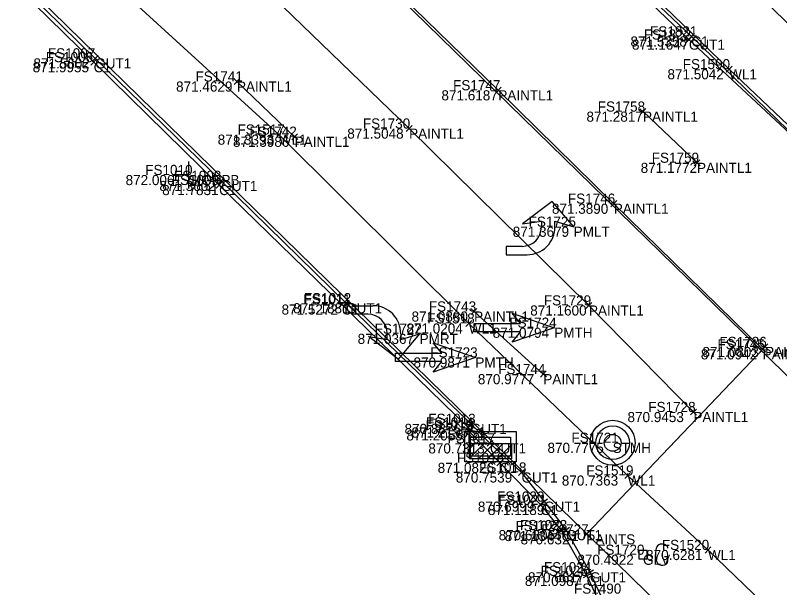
# Model space of a CAD drawing. Extents: x 1469677 to 1493262, y 375219 to 389293.
# Drawn here: x 1479502.2 to 1479592.9, y 379943 to 380010.9 of the extents above; entities that cross this region are included whole.
import ezdxf

# ---------------------------------------------------------------- set-up
doc = ezdxf.new("R2010")
doc.units = 0
for name, color, linetype in [('Building', 7, 'Continuous'), ('DR_X_Drive_Pipe', 7, 'Continuous'), ('DV_X_Text', 7, 'Continuous'), ('GK_Visualization', 7, 'Continuous'), ('PNTELEV', 7, 'Continuous'), ('RD_P_Text', 7, 'Continuous'), ('RW_P_Esmt_SW', 7, 'Continuous'), ('RW_P_Esmt_TMP', 7, 'Continuous'), ('RW_X_CL_20', 7, 'Continuous'), ('rw_x_right_of_way', 7, 'Continuous'), ('RW_X_Text', 7, 'Continuous'), ('SV_X_Mon_Cells_Found', 7, 'Continuous'), ('SV_X_Random_Point', 7, 'Continuous'), ('SV_X_Text', 7, 'Continuous'), ('SV_X_Text_Elevation', 7, 'Continuous')]:
    doc.layers.add(name, color=color, linetype=linetype)

msp = doc.modelspace()

# ---------------------------------------------------------------- linework, layer by layer
at = {"layer": 'Building'}
for points in [[(1479590.899, 379971.251), (1479573.223, 379988.536), (1479559.51, 380001.998), (1479539.567, 380021.405), (1479519.756, 380040.531), (1479501.596, 380058.123), (1479484.932, 380074.195)], [(1479582.673, 379963.807), (1479570.271, 379976.458), (1479548.912, 379997.458), (1479531.64, 380014.197), (1479515.852, 380030.017), (1479497.57, 380047.609), (1479484.703, 380060.356), (1479474.973, 380069.833)], [(1479528.47, 380003.039), (1479535.323, 379996.483)], [(1479576.693, 379999.465), (1479583.102, 379993.389)], [(1479556.633, 379975.739), (1479564.853, 379968.305)]]:
    msp.add_lwpolyline(points, dxfattribs=at)
at = {"layer": 'DR_X_Drive_Pipe'}
for points in [[(1479604.754, 379987.567), (1479586.915, 380004.501), (1479544.961, 380044.963), (1479522.598, 380067.181), (1479502.338, 380087.071)], [(1479473.217, 380054.881), (1479498.741, 380029.974), (1479514.505, 380014.087), (1479533.448, 379996.736), (1479556.003, 379974.32), (1479574.861, 379956.271), (1479584.403, 379947.432), (1479599.597, 379932.82), (1479630.106, 379903.783), (1479644.769, 379889.723), (1479654.209, 379882.356), (1479664.266, 379872.629), (1479692.509, 379845.847), (1479712.672, 379826.686), (1479730.739, 379809.851), (1479753.15, 379788.309), (1479771.842, 379770.542), (1479781.678, 379761.101)]]:
    msp.add_lwpolyline(points, dxfattribs=at)
at = {"layer": 'PNTELEV'}
for p, q in [((1479582.508, 380007.675), (1479581.776, 380008.356)), ((1479581.801, 380007.649), (1479582.483, 380008.381)), ((1479582.799, 380008.043), (1479582.081, 380008.739)), ((1479582.092, 380008.032), (1479582.788, 380008.751)), ((1479582.44, 380008.391), (1479582.44, 380008.391)), ((1479582.142, 380008.015), (1479582.142, 380008.015)), ((1479511.102, 380005.684), (1479511.816, 380004.984)), ((1479511.809, 380005.691), (1479511.109, 380004.977)), ((1479511.281, 380006.135), (1479511.997, 380005.436)), ((1479511.988, 380006.143), (1479511.29, 380005.427)), ((1479511.639, 380005.785), (1479511.639, 380005.785)), ((1479511.459, 380005.334), (1479511.459, 380005.334)), ((1479587.278, 380004.156), (1479586.552, 380004.845)), ((1479586.571, 380004.138), (1479587.259, 380004.863)), ((1479586.915, 380004.501), (1479586.915, 380004.501)), ((1479528.109, 380003.385), (1479528.831, 380002.693)), ((1479528.816, 380003.4), (1479528.124, 380002.678)), ((1479528.47, 380003.039), (1479528.47, 380003.039)), ((1479559.867, 380001.647), (1479559.153, 380002.348)), ((1479559.16, 380001.641), (1479559.86, 380002.354)), ((1479559.51, 380001.998), (1479559.51, 380001.998)), ((1479576.33, 379999.809), (1479577.056, 379999.121)), ((1479577.037, 379999.828), (1479576.349, 379999.102)), ((1479576.693, 379999.465), (1479576.693, 379999.465)), ((1479549.269, 379997.107), (1479548.555, 379997.808)), ((1479548.561, 379997.101), (1479549.263, 379997.814)), ((1479548.912, 379997.458), (1479548.912, 379997.458)), ((1479533.079, 379997.073), (1479533.817, 379996.398)), ((1479533.786, 379997.104), (1479533.11, 379996.367)), ((1479533.448, 379996.736), (1479533.448, 379996.736)), ((1479534.962, 379996.828), (1479535.684, 379996.137)), ((1479535.669, 379996.844), (1479534.977, 379996.121)), ((1479535.323, 379996.483), (1479535.323, 379996.483)), ((1479582.739, 379993.733), (1479583.465, 379993.045)), ((1479583.446, 379993.752), (1479582.758, 379993.026)), ((1479583.102, 379993.389), (1479583.102, 379993.389)), ((1479525.996, 379991.102), (1479526.71, 379990.403)), ((1479526.703, 379991.11), (1479526.003, 379990.395)), ((1479526.254, 379991.587), (1479526.972, 379990.89)), ((1479526.961, 379991.597), (1479526.265, 379990.88)), ((1479526.613, 379991.239), (1479526.613, 379991.239)), ((1479526.353, 379990.753), (1479526.353, 379990.753)), ((1479573.58, 379988.187), (1479572.866, 379988.886)), ((1479572.873, 379988.179), (1479573.573, 379988.894)), ((1479573.223, 379988.536), (1479573.223, 379988.536)), ((1479540.574, 379976.917), (1479541.29, 379976.22)), ((1479541.281, 379976.927), (1479540.583, 379976.21)), ((1479540.932, 379976.569), (1479540.932, 379976.569)), ((1479541.077, 379977.072), (1479541.791, 379976.372)), ((1479541.784, 379977.079), (1479541.084, 379976.365)), ((1479541.434, 379976.722), (1479541.434, 379976.722)), ((1479569.914, 379976.108), (1479570.628, 379976.808)), ((1479570.621, 379976.101), (1479569.921, 379976.815)), ((1479556.262, 379976.074), (1479557.004, 379975.403)), ((1479556.968, 379976.11), (1479556.298, 379975.368)), ((1479556.633, 379975.739), (1479556.633, 379975.739)), ((1479570.271, 379976.458), (1479570.271, 379976.458)), ((1479555.648, 379974.672), (1479556.358, 379973.967)), ((1479556.355, 379974.674), (1479555.651, 379973.965)), ((1479556.003, 379974.32), (1479556.003, 379974.32)), ((1479591.256, 379970.901), (1479590.542, 379971.6)), ((1479590.549, 379970.893), (1479591.249, 379971.608)), ((1479591.546, 379971.184), (1479590.822, 379971.874)), ((1479591.529, 379971.891), (1479590.839, 379971.168)), ((1479590.899, 379971.251), (1479590.899, 379971.251)), ((1479591.184, 379971.529), (1479591.184, 379971.529)), ((1479564.482, 379968.64), (1479565.224, 379967.969)), ((1479565.188, 379968.676), (1479564.518, 379967.934)), ((1479564.853, 379968.305), (1479564.853, 379968.305)), ((1479582.316, 379963.456), (1479583.03, 379964.157)), ((1479583.023, 379963.449), (1479582.323, 379964.164)), ((1479582.673, 379963.807), (1479582.673, 379963.807)), ((1479555.576, 379962.321), (1479556.292, 379961.623)), ((1479556.283, 379962.33), (1479555.585, 379961.614)), ((1479555.953, 379962.128), (1479555.831, 379961.135)), ((1479555.866, 379962.75), (1479556.584, 379962.054)), ((1479556.573, 379962.761), (1479555.877, 379962.043)), ((1479555.934, 379961.972), (1479555.934, 379961.972)), ((1479556.225, 379962.402), (1479556.225, 379962.402)), ((1479556.388, 379961.57), (1479555.396, 379961.693)), ((1479555.892, 379961.632), (1479555.892, 379961.632)), ((1479558.877, 379960.44), (1479558.167, 379959.736)), ((1479558.17, 379960.443), (1479558.874, 379959.733)), ((1479558.522, 379960.088), (1479558.522, 379960.088)), ((1479560.041, 379958.128), (1479559.329, 379957.427)), ((1479559.334, 379958.134), (1479560.036, 379957.421)), ((1479559.685, 379957.777), (1479559.685, 379957.777)), ((1479561.896, 379956.971), (1479562.63, 379956.292)), ((1479562.602, 379956.999), (1479561.924, 379956.264)), ((1479562.263, 379956.632), (1479562.263, 379956.632)), ((1479574.5, 379956.617), (1479575.222, 379955.925)), ((1479575.207, 379956.632), (1479574.515, 379955.91)), ((1479574.861, 379956.271), (1479574.861, 379956.271)), ((1479564.904, 379953.126), (1479564.186, 379952.429)), ((1479564.196, 379953.136), (1479564.894, 379952.419)), ((1479565.339, 379953.478), (1479564.549, 379952.866)), ((1479564.638, 379953.567), (1479565.25, 379952.777)), ((1479564.944, 379953.172), (1479564.944, 379953.172)), ((1479564.545, 379952.777), (1479564.545, 379952.777)), ((1479567.245, 379950.188), (1479567.855, 379949.396)), ((1479567.407, 379949.999), (1479566.627, 379949.375)), ((1479566.705, 379950.077), (1479567.329, 379949.296)), ((1479567.017, 379949.687), (1479567.017, 379949.687)), ((1479567.946, 379950.098), (1479567.154, 379949.487)), ((1479567.55, 379949.792), (1479567.55, 379949.792)), ((1479570.328, 379948.946), (1479569.604, 379949.636)), ((1479570.311, 379949.653), (1479569.621, 379948.929)), ((1479569.966, 379949.291), (1479569.966, 379949.291)), ((1479584.036, 379947.772), (1479584.77, 379947.093)), ((1479584.743, 379947.799), (1479584.063, 379947.065)), ((1479584.403, 379947.432), (1479584.403, 379947.432)), ((1479569.759, 379944.796), (1479570.247, 379943.923)), ((1479570.829, 379945.03), (1479569.959, 379944.537)), ((1479570.147, 379945.218), (1479570.641, 379944.349)), ((1479570.394, 379944.783), (1479570.394, 379944.783)), ((1479570.439, 379944.604), (1479569.567, 379944.115)), ((1479570.003, 379944.36), (1479570.003, 379944.36))]:
    msp.add_line(p, q, dxfattribs=at)
at = {"layer": 'RD_P_Text'}
for points in [[(1479620.557, 379971.482), (1479582.44, 380008.391), (1479569.122, 380021.058), (1479556.793, 380033.025), (1479540.187, 380049.375), (1479522.156, 380066.75), (1479503.679, 380084.635)], [(1479602.178, 379989.373), (1479582.142, 380008.015), (1479568.704, 380020.876), (1479556.358, 380032.756), (1479539.916, 380048.835), (1479521.67, 380066.459), (1479503.182, 380084.417)], [(1479465.43, 380051.173), (1479478.923, 380037.911), (1479495.631, 380021.427), (1479511.639, 380005.785), (1479526.613, 379991.239), (1479541.434, 379976.722), (1479556.225, 379962.402), (1479558.522, 379960.088), (1479562.263, 379956.632), (1479564.944, 379953.172), (1479567.55, 379949.792), (1479570.394, 379944.783), (1479571.863, 379941.541)], [(1479465.217, 380050.647), (1479478.531, 380037.631), (1479495.524, 380020.938), (1479511.459, 380005.334), (1479526.353, 379990.753), (1479540.932, 379976.569), (1479555.934, 379961.972), (1479555.892, 379961.632), (1479559.685, 379957.777), (1479564.545, 379952.777), (1479567.017, 379949.687), (1479570.003, 379944.36), (1479571.368, 379941.516)]]:
    msp.add_lwpolyline(points, dxfattribs=at)
at = {"layer": 'RW_P_Esmt_TMP'}
for p, q in [((1479565.898, 379988.802), (1479562.378, 379986.135)), ((1479568.458, 379985.802), (1479565.898, 379988.802)), ((1479562.378, 379986.135), (1479564.618, 379986.469)), ((1479564.618, 379986.469), (1479564.618, 379985.766)), ((1479566.218, 379985.802), (1479566.218, 379986.469)), ((1479566.218, 379986.469), (1479568.458, 379985.802)), ((1479560.458, 379985.802), (1479560.458, 379985.802)), ((1479568.458, 379985.802), (1479568.458, 379985.802)), ((1479562.321, 379983.469), (1479560.458, 379983.469)), ((1479560.458, 379983.469), (1479560.458, 379982.469)), ((1479560.458, 379982.469), (1479562.937, 379982.469)), ((1479542.163, 379975.422), (1479542.163, 379976.422)), ((1479542.163, 379976.422), (1479544.642, 379976.422)), ((1479544.026, 379975.422), (1479542.163, 379975.422)), ((1479562.153, 379974.315), (1479561.153, 379975.551)), ((1479561.153, 379975.551), (1479566.153, 379973.815)), ((1479556.653, 379973.315), (1479556.653, 379974.315)), ((1479556.653, 379974.315), (1479562.153, 379974.315)), ((1479556.653, 379973.815), (1479556.653, 379973.815)), ((1479566.153, 379973.815), (1479561.153, 379972.079)), ((1479566.153, 379973.815), (1479566.153, 379973.815)), ((1479542.163, 379973.089), (1479542.163, 379973.089)), ((1479546.323, 379972.422), (1479546.323, 379973.125)), ((1479550.163, 379973.089), (1479547.603, 379970.089)), ((1479547.923, 379973.089), (1479547.923, 379972.422)), ((1479547.923, 379972.422), (1479550.163, 379973.089)), ((1479550.163, 379973.089), (1479550.163, 379973.089)), ((1479562.153, 379973.315), (1479556.653, 379973.315)), ((1479561.153, 379972.079), (1479562.153, 379973.315)), ((1479547.603, 379970.089), (1479544.083, 379972.755)), ((1479544.083, 379972.755), (1479546.323, 379972.422)), ((1479552.784, 379970.784), (1479551.784, 379972.02)), ((1479551.784, 379972.02), (1479556.784, 379970.284)), ((1479547.284, 379969.784), (1479547.284, 379970.784)), ((1479547.284, 379970.784), (1479552.784, 379970.784)), ((1479547.284, 379970.284), (1479547.284, 379970.284)), ((1479556.784, 379970.284), (1479551.784, 379968.548)), ((1479556.784, 379970.284), (1479556.784, 379970.284)), ((1479552.784, 379969.784), (1479547.284, 379969.784)), ((1479551.784, 379968.548), (1479552.784, 379969.784))]:
    msp.add_line(p, q, dxfattribs=at)
for centre, radius, start, end in [((1479562.321, 379985.766), 2.297, 270, 0), ((1479562.937, 379985.75), 3.281, 270, 0.90849), ((1479544.642, 379973.141), 3.281, 359.09151, 90), ((1479544.026, 379973.125), 2.297, 360, 90)]:
    msp.add_arc(centre, radius, start, end, dxfattribs=at)
at = {"layer": 'RW_X_CL_20'}
for p, q in [((1479573.085, 379962.155), (1479573.085, 379962.155)), ((1479558.584, 379961.489), (1479558.584, 379961.489)), ((1479558.584, 379960.822), (1479558.584, 379960.822)), ((1479573.085, 379960.155), (1479573.085, 379960.155)), ((1479573.085, 379960.155), (1479573.085, 379960.155)), ((1479573.085, 379960.155), (1479573.085, 379960.155)), ((1479556.209, 379959.697), (1479556.209, 379959.697)), ((1479558.584, 379960.072), (1479558.584, 379960.072)), ((1479558.584, 379960.072), (1479558.584, 379960.072)), ((1479558.584, 379959.697), (1479558.584, 379959.697)), ((1479560.959, 379959.697), (1479560.959, 379959.697)), ((1479558.584, 379958.572), (1479558.584, 379958.572)), ((1479558.584, 379957.906), (1479558.584, 379957.906)), ((1479573.085, 379958.155), (1479573.085, 379958.155))]:
    msp.add_line(p, q, dxfattribs=at)
msp.add_circle((1479573.085, 379960.155), 2, dxfattribs=at)
at = {"layer": 'rw_x_right_of_way'}
for p, q in [((1479522.707, 379993.541), (1479522.707, 379990.341)), ((1479522.707, 379991.941), (1479521.107, 379991.941))]:
    msp.add_line(p, q, dxfattribs=at)
at = {"layer": 'RW_X_Text'}
for points in [[(1479579.657, 379947.631), (1479579.638, 379947.729), (1479579.579, 379947.828), (1479579.48, 379947.926), (1479579.343, 379948.044), (1479579.244, 379948.084), (1479579.165, 379948.103), (1479579.047, 379948.123), (1479578.811, 379948.123), (1479578.713, 379948.103), (1479578.653, 379948.084), (1479578.575, 379948.044), (1479578.417, 379947.926), (1479578.319, 379947.788), (1479578.26, 379947.631), (1479578.22, 379947.414), (1479578.181, 379947.099), (1479578.181, 379946.686), (1479578.201, 379946.351), (1479578.28, 379946.095), (1479578.398, 379945.859), (1479578.496, 379945.78), (1479578.614, 379945.702), (1479578.831, 379945.623), (1479579.047, 379945.623), (1479579.264, 379945.662), (1479579.343, 379945.702), (1479579.421, 379945.741), (1479579.5, 379945.82), (1479579.579, 379945.938), (1479579.657, 379946.115), (1479579.657, 379946.607), (1479579.244, 379946.607)], [(1479576.194, 379946.366), (1479577.194, 379946.366), (1479577.194, 379947.366), (1479576.194, 379947.366), (1479576.194, 379946.366)]]:
    msp.add_lwpolyline(points, dxfattribs=at)
at = {"layer": 'SV_X_Mon_Cells_Found'}
for points in [[(1477206.544, 382340.781), (1479657.335, 379947.979), (1480466.338, 379191.878)], [(1477164.629, 382297.849), (1479615.888, 379904.59), (1480413.414, 379159.216)]]:
    msp.add_lwpolyline(points, dxfattribs=at)
at = {"layer": 'SV_X_Random_Point'}
for p, q in [((1479556.084, 379958.314), (1479557.838, 379960.072)), ((1479556.084, 379959.447), (1479556.708, 379960.072)), ((1479557.14, 379958.239), (1479558.968, 379960.072)), ((1479558.269, 379958.239), (1479560.098, 379960.072)), ((1479559.399, 379958.239), (1479561.084, 379959.929)), ((1479560.529, 379958.239), (1479561.084, 379958.796))]:
    msp.add_line(p, q, dxfattribs=at)
for points in [[(1479555.542, 379961.49), (1479561.626, 379961.49), (1479561.626, 379957.906), (1479555.542, 379957.906)], [(1479556.209, 379960.822), (1479560.959, 379960.822), (1479560.959, 379958.572), (1479556.209, 379958.572)], [(1479556.084, 379960.072), (1479561.084, 379960.072), (1479561.084, 379958.239), (1479556.084, 379958.239)]]:
    msp.add_lwpolyline(points, close=True, dxfattribs=at)
for radius in [2.667, 2, 1]:
    msp.add_circle((1479573.085, 379960.155), radius, dxfattribs=at)
at = {"layer": 'SV_X_Text'}
msp.add_lwpolyline([(1479591.184, 379971.529), (1479569.966, 379949.291)], dxfattribs=at)
at = {"layer": 'SV_X_Text_Elevation'}
msp.add_line((1478152.942, 381374.848), (1479636.611, 379926.284), dxfattribs=at)

# ---------------------------------------------------------------- texts
at = {"layer": 'DV_X_Text'}
for s, height, p in [('871.5358', 1.2, (1479575.203, 380007.191)), ('871.1647', 1.2, (1479575.378, 380006.815)), ('871.5602', 1.2, (1479504.308, 380004.585)), ('871.9955', 1.2, (1479504.213, 380004.134)), ('871.5042', 1.2, (1479579.593, 380003.301)), ('871.4629', 1.2, (1479521.243, 380001.839)), ('871.6187', 1.2, (1479552.756, 380000.798)), ('871.2817', 1.2, (1479569.977, 379998.265)), ('871.5048', 1.2, (1479541.571, 379996.258)), ('871.3393', 1.2, (1479526.183, 379995.536)), ('871.3986', 1.2, (1479528.001, 379995.283)), ('871.1772', 1.2, (1479576.414, 379992.189)), ('872.0061', 1.2, (1479515.25, 379990.741)), ('871.3602', 1.2, (1479519.263, 379990.039)), ('871.7831', 1.2, (1479519.596, 379989.553)), ('871.3890', 1.2, (1479565.873, 379987.336)), ('871.3679', 1.2, (1479561.221, 379984.602)), ('871.5272', 1.2, (1479533.771, 379975.369)), ('871.1881', 1.2, (1479535.15, 379975.522)), ('871.1600', 1.2, (1479563.299, 379975.258)), ('871.0880', 1.2, (1479549.207, 379974.539)), ('871.0204', 1.2, (1479548.596, 379973.12)), ('871.0794', 1.2, (1479558.841, 379972.615)), ('871.0367', 1.2, (1479542.803, 379971.889)), ('871.0942', 1.2, (1479583.558, 379970.051)), ('871.0803', 1.2, (1479583.749, 379970.329)), ('870.9871', 1.2, (1479549.44, 379969.084)), ('870.9777', 1.2, (1479557.077, 379967.105)), ('870.9453', 1.2, (1479574.85, 379962.607)), ('870.8876', 1.2, (1479548.374, 379961.202)), ('871.2135', 1.2, (1479549.199, 379960.772)), ('871.2055', 1.2, (1479548.589, 379960.432)), ('870.7775', 1.2, (1479565.347, 379958.955)), ('870.7313', 1.2, (1479551.2, 379958.888)), ('870.6992', 0.2, (1479557.277, 379959.872)), ('871.0826', 1.2, (1479552.307, 379956.577)), ('870.7539', 1.2, (1479554.459, 379955.432)), ('870.7363', 1.2, (1479567.047, 379955.071)), ('870.6999', 1.2, (1479557.083, 379951.972)), ('871.1189', 1.2, (1479558.273, 379951.577)), ('870.6806', 1.2, (1479559.547, 379948.592)), ('871.1344', 1.2, (1479560.263, 379948.487)), ('870.6327', 1.2, (1479562.152, 379948.091)), ('870.6281', 1.2, (1479577.059, 379946.232)), ('870.4922', 1.2, (1479568.899, 379945.666)), ('870.6617', 1.2, (1479563.034, 379943.583)), ('871.0987', 1.2, (1479562.662, 379943.16))]:
    msp.add_text(s, height=height, dxfattribs=at).set_placement(p)
at = {"layer": 'GK_Visualization'}
for s, height, p in [('C1', 1.2, (1479582.44, 380007.191)), ('GUT1', 1.2, (1479582.142, 380006.815)), ('GUT1', 1.2, (1479511.639, 380004.585)), ('C1', 1.2, (1479511.459, 380004.134)), ('WL1', 1.2, (1479586.915, 380003.301)), ('PAINTL1', 1.2, (1479528.47, 380001.839)), ('PAINTL1', 1.2, (1479559.51, 380000.798)), ('PAINTL1', 1.2, (1479576.693, 379998.265)), ('PAINTL1', 1.2, (1479548.912, 379996.258)), ('WL1', 1.2, (1479533.448, 379995.536)), ('PAINTL1', 1.2, (1479535.323, 379995.283)), ('PAINTL1', 1.2, (1479583.102, 379992.189)), ('SIGNPB', 1.2, (1479522.707, 379990.741)), ('GUT1', 1.2, (1479526.613, 379990.039)), ('C1', 1.2, (1479526.353, 379989.553)), ('PAINTL1', 1.2, (1479573.223, 379987.336)), ('PMLT', 1.2, (1479568.458, 379984.602)), ('C1', 1.2, (1479540.932, 379975.369)), ('GUT1', 1.2, (1479541.434, 379975.522)), ('PAINTL1', 1.2, (1479556.633, 379974.539)), ('PAINTL1', 1.2, (1479570.271, 379975.258)), ('WL1', 1.2, (1479556.003, 379973.12)), ('PMTH', 1.2, (1479566.153, 379972.615)), ('PMRT', 1.2, (1479550.163, 379971.889)), ('PAINTL1', 1.2, (1479590.899, 379970.051)), ('PAINTS', 1.2, (1479591.184, 379970.329)), ('PMTH', 1.2, (1479556.784, 379969.084)), ('PAINTL1', 1.2, (1479564.853, 379967.105)), ('PAINTL1', 1.2, (1479582.673, 379962.607)), ('C1', 1.2, (1479555.934, 379960.772)), ('GUT1', 1.2, (1479556.225, 379961.202)), ('C1', 1.2, (1479555.892, 379960.432)), ('STMH', 1.2, (1479573.085, 379958.955)), ('CB-3', 0.2, (1479558.584, 379959.872)), ('GUT1', 1.2, (1479558.522, 379958.888)), ('C1', 1.2, (1479559.685, 379956.577)), ('GUT1', 1.2, (1479562.263, 379955.432)), ('WL1', 1.2, (1479574.861, 379955.071)), ('GUT1', 1.2, (1479564.944, 379951.972)), ('C1', 1.2, (1479564.545, 379951.577)), ('C1', 1.2, (1479567.017, 379948.487)), ('GUT1', 1.2, (1479567.55, 379948.592)), ('PAINTS', 1.2, (1479569.966, 379948.091)), ('WL1', 1.2, (1479584.403, 379946.232)), ('GLV', 1.2, (1479576.694, 379945.666)), ('GUT1', 1.2, (1479570.394, 379943.583)), ('C1', 1.2, (1479570.003, 379943.16))]:
    msp.add_text(s, height=height, dxfattribs=at).set_placement(p)
at = {"layer": 'RW_P_Esmt_SW'}
for s, height, p in [('FS1822', 1.2, (1479576.786, 380008.015)), ('FS1821', 1.2, (1479577.525, 380008.391)), ('FS1006', 1.2, (1479505.772, 380005.334)), ('FS1007', 1.2, (1479506.027, 380005.785)), ('FS1590', 1.2, (1479581.407, 380004.501)), ('FS1741', 1.2, (1479523.546, 380003.039)), ('FS1747', 1.2, (1479554.135, 380001.998)), ('FS1758', 1.2, (1479571.318, 379999.465)), ('FS1730', 1.2, (1479543.423, 379997.458)), ('FS1517', 1.2, (1479528.536, 379996.736)), ('FS1742', 1.2, (1479529.957, 379996.483)), ('FS1759', 1.2, (1479577.727, 379993.389)), ('FS1010', 1.2, (1479517.578, 379991.941)), ('FS1009', 1.2, (1479520.732, 379990.753)), ('FS1008', 1.2, (1479520.992, 379991.239)), ('FS1746', 1.2, (1479567.772, 379988.536)), ('FS1725', 1.2, (1479563.111, 379985.802)), ('FS1011', 1.2, (1479536.358, 379976.569)), ('FS1012', 1.2, (1479536.418, 379976.722)), ('FS1729', 1.2, (1479564.915, 379976.458)), ('FS1743', 1.2, (1479551.258, 379975.739)), ('FS1518', 1.2, (1479551.082, 379974.32)), ('FS1724', 1.2, (1479560.815, 379973.815)), ('FS1722', 1.2, (1479544.825, 379973.089)), ('FS1745', 1.2, (1479585.524, 379971.251)), ('FS1726', 1.2, (1479585.761, 379971.529)), ('FS1723', 1.2, (1479551.437, 379970.284)), ('FS1744', 1.2, (1479559.487, 379968.305)), ('FS1728', 1.2, (1479577.317, 379963.807)), ('FS1014', 1.2, (1479550.918, 379961.972)), ('FS1013', 1.2, (1479551.2, 379962.402)), ('FS1015', 1.2, (1479550.867, 379961.632)), ('FS1017', 1.2, (1479553.497, 379960.088)), ('FS1721', 1.2, (1479568.189, 379960.155)), ('FS1019', 0.2, (1479557.745, 379960.072)), ('FS1016', 1.2, (1479554.584, 379957.777)), ('FS1018', 1.2, (1479557.228, 379956.632)), ('FS1519', 1.2, (1479569.94, 379956.271)), ('FS1020', 1.2, (1479559.361, 379953.172)), ('FS1021', 1.2, (1479559.517, 379952.777)), ('FS1022', 1.2, (1479561.547, 379949.687)), ('FS1023', 1.2, (1479562.071, 379949.792)), ('FS1727', 1.2, (1479564.619, 379949.291)), ('FS1520', 1.2, (1479578.933, 379947.432)), ('FS1720', 1.2, (1479571.243, 379946.866)), ('FS1024', 1.2, (1479564.924, 379944.783)), ('FS1025', 1.2, (1479564.524, 379944.36)), ('FS1490', 1.2, (1479568.493, 379942.241))]:
    msp.add_text(s, height=height, dxfattribs=at).set_placement(p)

doc.saveas('drawing.dxf')
